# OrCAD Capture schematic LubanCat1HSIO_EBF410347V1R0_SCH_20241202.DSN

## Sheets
1 04 邮票孔连接器: size A4; title: 野火鲁班猫1HS.邮票孔核心板; rev: V1.0; note: 邮票孔连接器; note: https://yehuosm.tmall.com
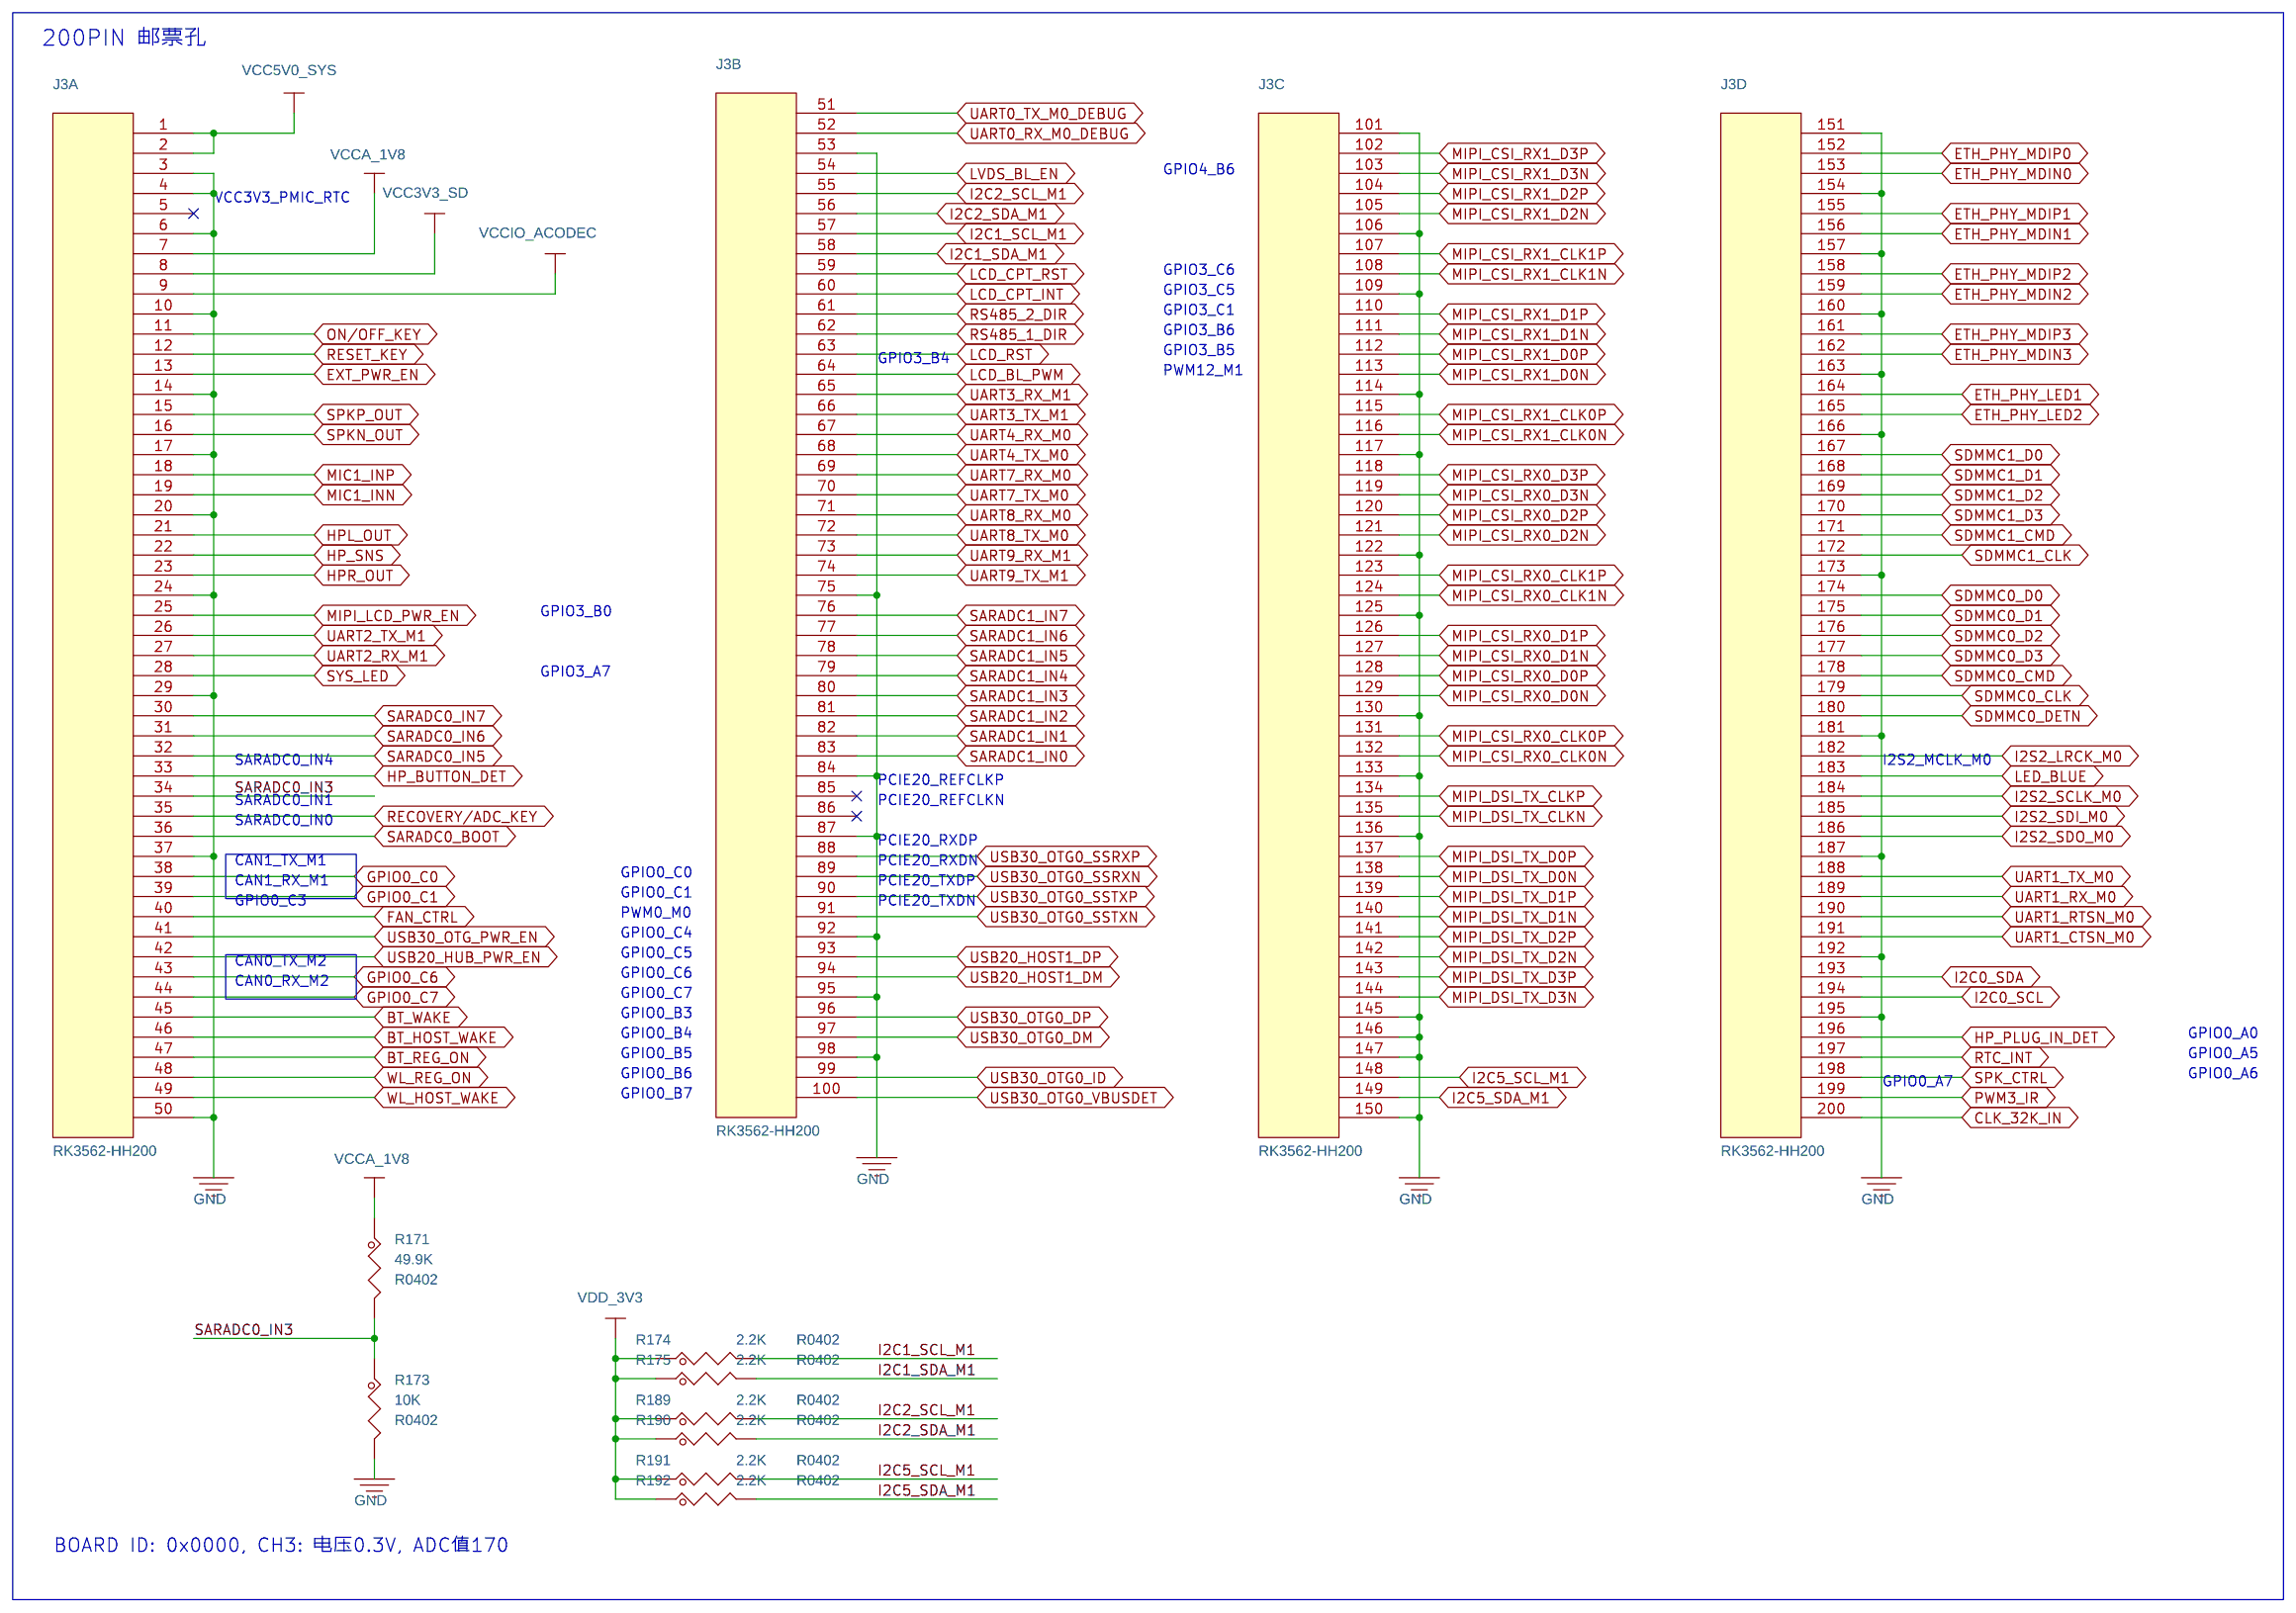
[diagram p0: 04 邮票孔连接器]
2 12 UART/RS232/RS485: size A4; title: 野火鲁班猫1HS.邮票孔底板; note: UART/RS232/RS485
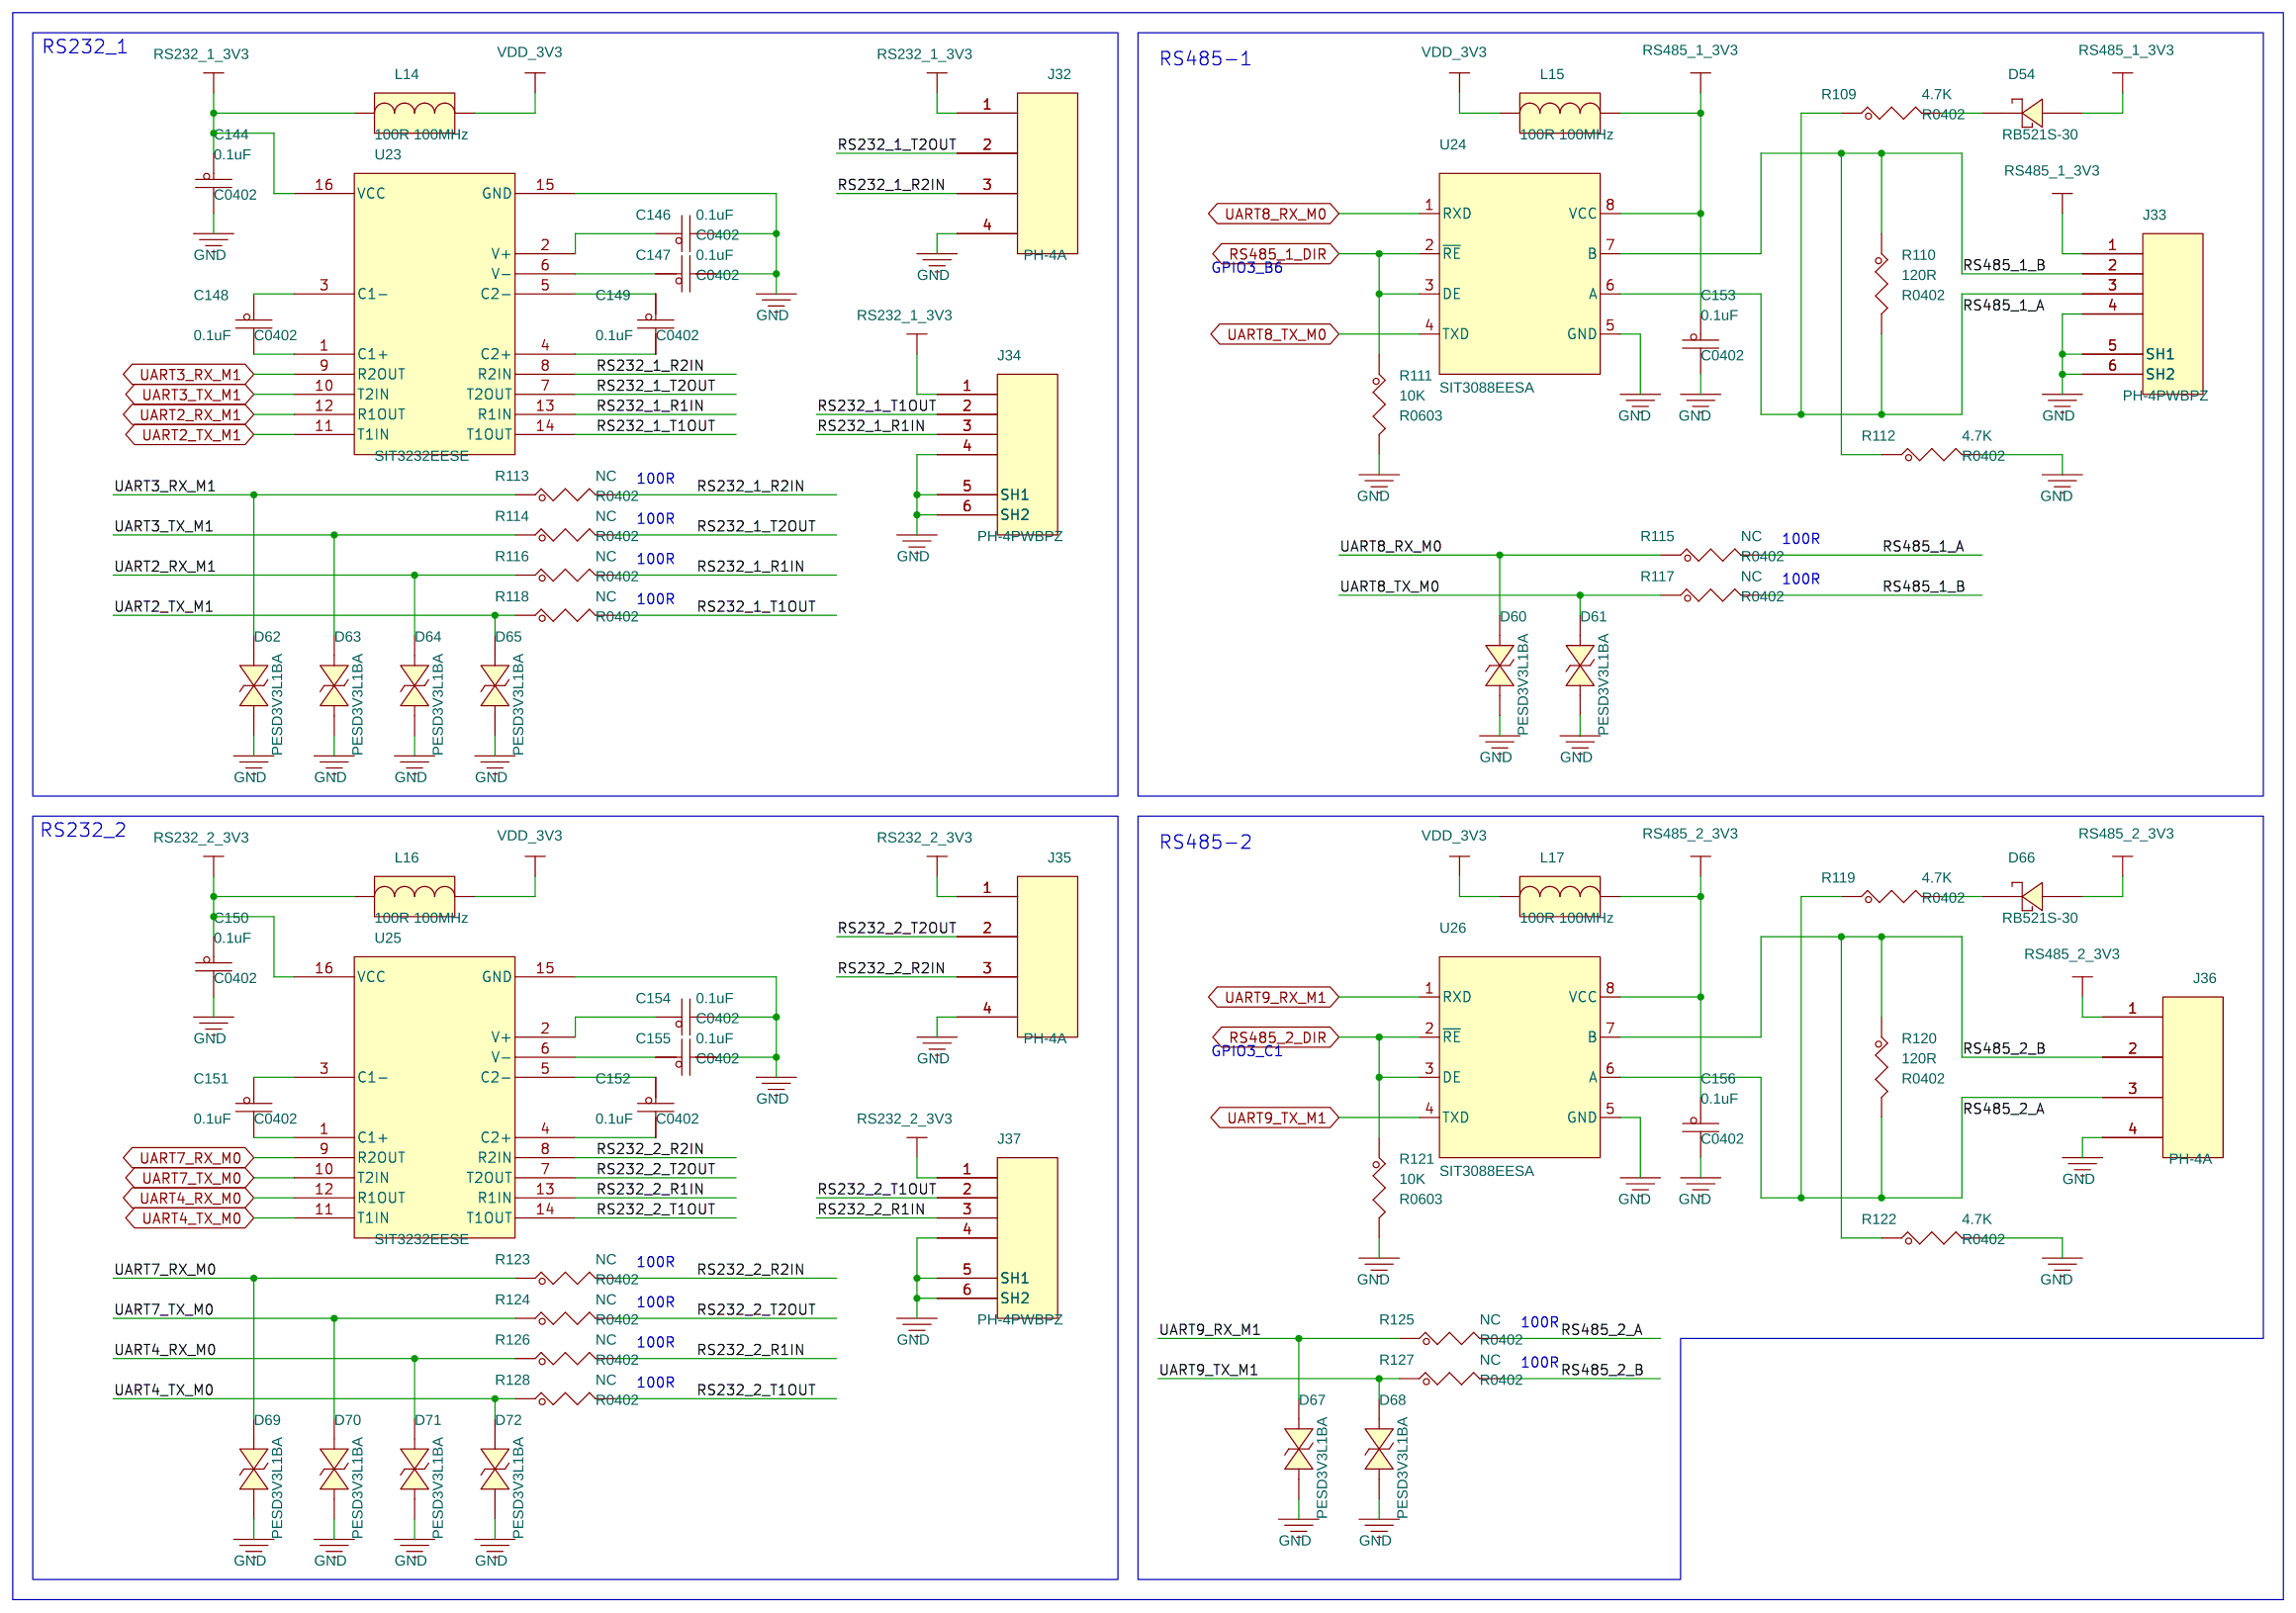
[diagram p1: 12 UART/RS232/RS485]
3 07 USB3.0 OTG/USB2.0 HUB/DEBUG: size A3; title: 野火鲁班猫1HS.邮票孔底板; note: USB3.0 OTG/USB2.0 HUB/DEBUG
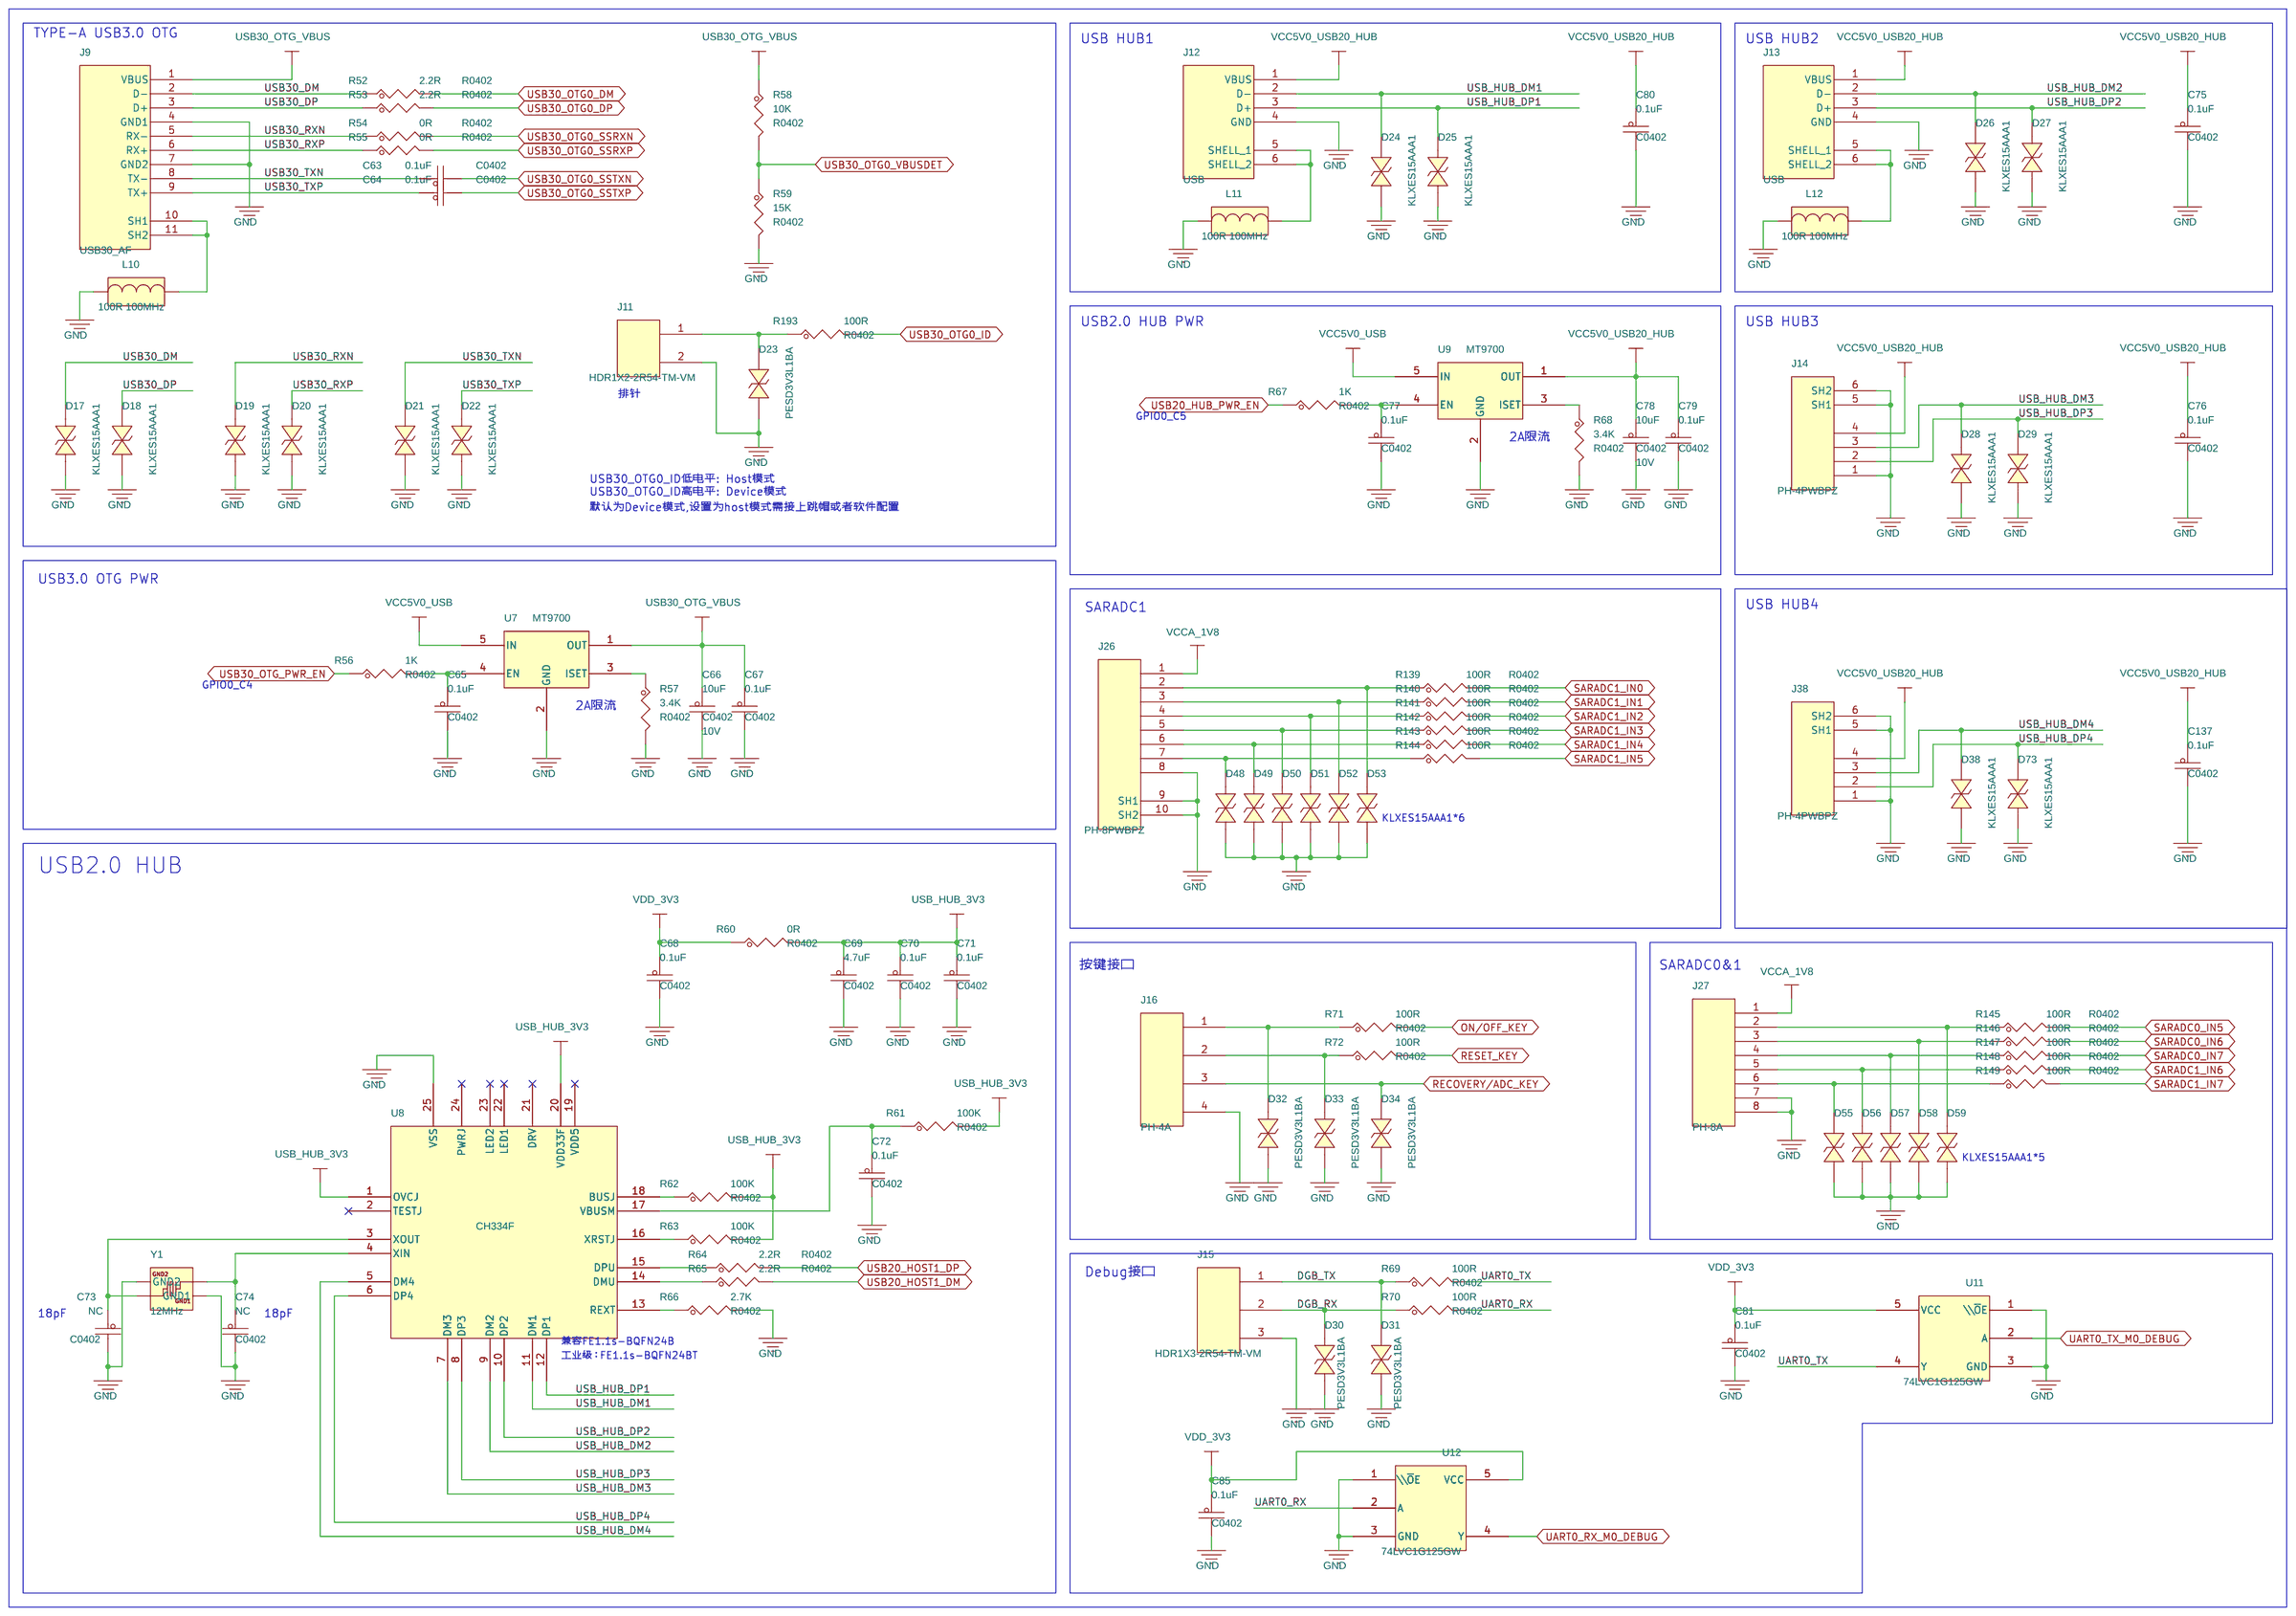
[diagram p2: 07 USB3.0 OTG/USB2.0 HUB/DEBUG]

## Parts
sheet 04 邮票孔连接器
J3  RK3562-HH200  [HH200-0R90-48R1X48R1-B]  (sections A,B,C,D)
R171  49.9K  [R0402]
R173  10K  [R0402]
R174  2.2K  [R0402]
R175  2.2K  [R0402]
R189  2.2K  [R0402]
R190  2.2K  [R0402]
R191  2.2K  [R0402]
R192  2.2K  [R0402]
sheet 07 USB3.0 OTG/USB2.0 HUB/DEBUG
C63  0.1uF  [C0402]
C64  0.1uF  [C0402]
C65  0.1uF  [C0402]
C66  10uF  [C0402]
C67  0.1uF  [C0402]
C68  0.1uF  [C0402]
C69  4.7uF  [C0402]
C70  0.1uF  [C0402]
C71  0.1uF  [C0402]
C72  0.1uF  [C0402]
C73  NC  [C0402]
C74  NC  [C0402]
C75  0.1uF  [C0402]
C76  0.1uF  [C0402]
C77  0.1uF  [C0402]
C78  10uF  [C0402]
C79  0.1uF  [C0402]
C80  0.1uF  [C0402]
C81  0.1uF  [C0402]
C85  0.1uF  [C0402]
C137  0.1uF  [C0402]
D17  KLXES15AAA1  [ES0402]
D18  KLXES15AAA1  [ES0402]
D19  KLXES15AAA1  [ES0402]
D20  KLXES15AAA1  [ES0402]
D21  KLXES15AAA1  [ES0402]
D22  KLXES15AAA1  [ES0402]
D23  PESD3V3L1BA  [sod323_t]
D24  KLXES15AAA1  [ES0402]
D25  KLXES15AAA1  [ES0402]
D26  KLXES15AAA1  [ES0402]
D27  KLXES15AAA1  [ES0402]
D28  KLXES15AAA1  [ES0402]
D29  KLXES15AAA1  [ES0402]
D30  PESD3V3L1BA  [sod323_t]
D31  PESD3V3L1BA  [sod323_t]
D32  PESD3V3L1BA  [sod323_t]
D33  PESD3V3L1BA  [sod323_t]
D34  PESD3V3L1BA  [sod323_t]
D38  KLXES15AAA1  [ES0402]
D48  KLXES15AAA1  [ES0402]
D49  KLXES15AAA1  [ES0402]
D50  KLXES15AAA1  [ES0402]
D51  KLXES15AAA1  [ES0402]
D52  KLXES15AAA1  [ES0402]
D53  KLXES15AAA1  [ES0402]
D55  KLXES15AAA1  [ES0402]
D56  KLXES15AAA1  [ES0402]
D57  KLXES15AAA1  [ES0402]
D58  KLXES15AAA1  [ES0402]
D59  KLXES15AAA1  [ES0402]
D73  KLXES15AAA1  [ES0402]
J9  USB30_AF  [USB9-A-16R5X14R45-TM]
J11  HDR1X2-2R54-TM-VM  [HDR1X2-2R54-TM-VM]
J12  USB  [USB-A-SM]
J13  USB  [USB-A-SM]
J14  PH-4PWBPZ  [ph2r0-a-1x4]
J15  HDR1X3-2R54-TM-VM  [HDR1X3-2R54-TM-VM]
J16  PH-4A  [PH-1X4-2P0]
J26  PH-8PWBPZ  [PH2R0-A-1X8]
J27  PH-8A  [ph-1x8-2p0]
J38  PH-4PWBPZ  [ph2r0-a-1x4]
L10  100R 100MHz  [L0603]
L11  100R 100MHz  [L0603]
L12  100R 100MHz  [L0603]
R52  2.2R  [R0402]
R53  2.2R  [R0402]
R54  0R  [R0402]
R55  0R  [R0402]
R56  1K  [R0402]
R57  3.4K  [R0402]
R58  10K  [R0402]
R59  15K  [R0402]
R60  0R  [R0402]
R61  100K  [R0402]
R62  100K  [R0402]
R63  100K  [R0402]
R64  2.2R  [R0402]
R65  2.2R  [R0402]
R66  2.7K  [R0402]
R67  1K  [R0402]
R68  3.4K  [R0402]
R69  100R  [R0402]
R70  100R  [R0402]
R71  100R  [R0402]
R72  100R  [R0402]
R139  100R  [R0402]
R140  100R  [R0402]
R141  100R  [R0402]
R142  100R  [R0402]
R143  100R  [R0402]
R144  100R  [R0402]
R145  100R  [R0402]
R146  100R  [R0402]
R147  100R  [R0402]
R148  100R  [R0402]
R149  100R  [R0402]
R193  100R  [R0402]
U7  MT9700  [SOT23-5]
U8  CH334F  [QFN24]
U9  MT9700  [SOT23-5]
U11  74LVC1G125GW  [SOT-353]
U12  74LVC1G125GW  [SOT-353]
Y1  12MHz  [3225]
sheet 12 UART/RS232/RS485
C144  0.1uF  [C0402]
C146  0.1uF  [C0402]
C147  0.1uF  [C0402]
C148  0.1uF  [C0402]
C149  0.1uF  [C0402]
C150  0.1uF  [C0402]
C151  0.1uF  [C0402]
C152  0.1uF  [C0402]
C153  0.1uF  [C0402]
C154  0.1uF  [C0402]
C155  0.1uF  [C0402]
C156  0.1uF  [C0402]
D54  RB521S-30  [SOD523]
D60  PESD3V3L1BA  [sod323_t]
D61  PESD3V3L1BA  [sod323_t]
D62  PESD3V3L1BA  [sod323_t]
D63  PESD3V3L1BA  [sod323_t]
D64  PESD3V3L1BA  [sod323_t]
D65  PESD3V3L1BA  [sod323_t]
D66  RB521S-30  [SOD523]
D67  PESD3V3L1BA  [sod323_t]
D68  PESD3V3L1BA  [sod323_t]
D69  PESD3V3L1BA  [sod323_t]
D70  PESD3V3L1BA  [sod323_t]
D71  PESD3V3L1BA  [sod323_t]
D72  PESD3V3L1BA  [sod323_t]
J32  PH-4A  [PH-1X4-2P0]
J33  PH-4PWBPZ  [ph2r0-a-1x4]
J34  PH-4PWBPZ  [ph2r0-a-1x4]
J35  PH-4A  [PH-1X4-2P0]
J36  PH-4A  [PH-1X4-2P0]
J37  PH-4PWBPZ  [ph2r0-a-1x4]
L14  100R 100MHz  [L0603]
L15  100R 100MHz  [L0603]
L16  100R 100MHz  [L0603]
L17  100R 100MHz  [L0603]
R109  4.7K  [R0402]
R110  120R  [R0402]
R111  10K  [R0603]
R112  4.7K  [R0402]
R113  NC  [R0402]
R114  NC  [R0402]
R115  NC  [R0402]
R116  NC  [R0402]
R117  NC  [R0402]
R118  NC  [R0402]
R119  4.7K  [R0402]
R120  120R  [R0402]
R121  10K  [R0603]
R122  4.7K  [R0402]
R123  NC  [R0402]
R124  NC  [R0402]
R125  NC  [R0402]
R126  NC  [R0402]
R127  NC  [R0402]
R128  NC  [R0402]
U23  SIT3232EESE  [SOIC16]
U24  SIT3088EESA  [SOP8]
U25  SIT3232EESE  [SOIC16]
U26  SIT3088EESA  [SOP8]

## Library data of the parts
J3 = RK3562-HH200: 备注: 鲁班猫1HS; 规格: RK3562邮票孔核心板 引脚数量200P 引脚间距0.9mm 尺寸48.1x48.1mm; 类别: 邮票孔核心板; 品牌: 野火; 生命周期: 量产; 条码: EBFCIS240902134638
R171 = RES: 规格: 贴片电阻49.9K 1% 1/16W 0402; 规格编号: RMC040249.9K1%N; 规格书: 幸亚电阻.pdf; 价格: 0.015936; 类别: 贴片电阻0402; 品牌: 幸亚; 生命周期: 量产; 条码: EBF29070257
R58 R173 = RES: 规格: 贴片电阻10K 1% 1/16W 0402; 规格编号: 0402WGF1002TCE; 规格书: 厚声-无铅厚膜电阻.pdf; 价格: 0.002773; 类别: 贴片电阻0402; 品牌: 厚声; 生命周期: 量产; 条码: EBF29070046
R174 R175 R189-R192 = RES: 规格: 贴片电阻2.2K 1% 1/16W 0402; 规格编号: RI0402L2201FT; 规格书: 合科泰-RI系列电阻.pdf; 类别: 贴片电阻0402; 品牌: 合科泰; 生命周期: 量产; 条码: EBF29070051
C63-C65 C67 C68 C70-C72 C75-C77 C79-C81 C85 C137 C144 C146-C156 = CAP_NP: voltage: 10V; 备注: H743挑战者; 规格: 贴片电容0.1uF 10% 10V X7R 0402; 规格编号: 0402B104K100NT; 规格书: 风华电容.pdf; 价格: 0.003175; 类别: 贴片电容0402; 品牌: 风华; 生命周期: 量产; 条码: EBFCIS230603155031
C66 C78 = CAP_NP: Voltage: 10V; 规格: 贴片电容10uF 20% 10V X5R 0402; 规格编号: CL05A106MP8NUB8; 规格书: 三星电容.pdf; 价格: 0.518415; 类别: 贴片电容0402; 品牌: 三星; 生命周期: 量产; 条码: EBF29060247
C69 = CAP_NP: voltage: 10V; 规格: 贴片电容4.7uF 10% 10V X5R 0402; 规格编号: CC0402KRX5R6BB475; 规格书: 国巨-贴片电容.pdf; 价格: 0.059058; 类别: 贴片电容0402; 品牌: 国巨; 生命周期: 量产; 条码: EBF29060248
C73 C74 = CAP_NP: 规格: 贴片电容NC 预留; 类别: 贴片电容0402; 条码: EBF29060149
D17-D22 D24-D29 D38 D48-D53 D55-D59 D73 = DIODE_BI-DIR_TRIG: 规格: 用于 USB3.0、HDMI 0.5pF、5V、±15kV ESD 保护二极管; 规格书: KLXES15AAA1.pdf; 价格: 0.09719; 类别: 贴片ESD; 品牌: 永裕泰; 生命周期: 量产; 条码: EBF29140063
D23 D30-D34 D60-D65 D67-D72 = DIODE_BI-DIR_TRIG: 规格: 防静电保护ESD二极管 箝位电压26V 击穿电压5.8V 反向关断电压3.3V; 规格编号: PESD3V3L1BA 115; 规格书: 安世-PESD3V3L1BA-115.pdf; 价格: 0.31497; 类别: 贴片ESD; 品牌: 安世; 生命周期: 量产; 丝印: AB; 条码: EBF29140003
J9 = USB30_AF: 备注: RK3566广告机; 规格: USB3.0 Type-A 母座 AF 90°弯插 蓝胶 触点数量9; 规格编号: USB-301WD-ARY; 规格书: 讯普_USB3.0-TYPE-A母座弯插.pdf; 类别: USB接口; 品牌: 讯普; 生命周期: 量产; 条码: EBFCIS230517183858
J11 = 1X2PIN: 规格: 蓝色直插单排排针 总PIN数2 间距2.54mm; 规格编号: HDR1X2-2R54-TM-VM-BLUE; 规格书: 州日_单排针_直插_2P54.pdf; 价格: 0.02; 类别: 2.54mm直插单排排针; 品牌: 州日; 生命周期: 量产; 条码: EBF29020019
J12 J13 = USB_Conn.-Fem-TypeA-TH-RA: 规格: Type-A 母座 AF90°弯插 白胶 卷边有后盖 铁壳 触点数量4 额定电流1.5A; 规格编号: USB-U212-BJS; 规格书: TYPE-A母座AF90°弯插白胶卷边有后盖铁壳.pdf; 类别: USB接口; 品牌: 汉博; 生命周期: 量产; 条码: EBF29040127
J14 J33 J34 J37 J38 = 1X4PIN_SH: 规格: 间距：2mm 插针结构：1x4P 排数：1 每排PIN数：4 公母：公型插针 安装方式：卧贴 额定电流：2A 工作温度范围：-25℃~+85℃; 规格书: 博穆精密_PH2.0-A.pdf; 价格: 0.23158; 类别: PH连接器; 品牌: 博穆精密; 生命周期: 量产; 条码: EBF29040117
J15 = 1X3PIN: 规格: 蓝色直插单排排针 总PIN数3 间距2.54mm; 规格编号: HDR1X3-2R54-TM-VM-BLUE; 规格书: 州日_单排针_直插_2P54.pdf; 价格: 0.06; 类别: 2.54mm直插单排排针; 品牌: 州日; 生命周期: 量产; 条码: EBF29020046
J16 J32 J35 J36 = 1X4PIN: 规格: 直针PH2.0-4P 间距2.0MM 拔插式 接插件; 规格书: 博穆精密-PH2.0.pdf; 价格: 0.017; 可替代料: EBF29020025; 类别: PH连接器; 品牌: 博穆精密; 生命周期: 量产; 条码: EBF29020025
J26 = 1X8PIN_SH: 备注: RK3562邮票孔底板; 规格: 间距：2mm 插针结构：1x8P 排数：1 每排PIN数：8 公母：公型插针 安装方式：卧贴 额定电流：2A 工作温度范围：-25℃~+85℃; 规格书: 博穆精密_PH2.0-A.pdf; 价格: 0.648177; 类别: PH连接器; 品牌: 博穆精密; 生命周期: 量产; 条码: EBFCIS230829011841
J27 = 1X8PIN: 备注: RK3562邮票孔底板; 规格: 直针PH2.0-8P 间距2.0MM 拔插式 接插件; 规格书: 博穆精密-PH2.0.pdf; 价格: 0.206072; 类别: PH连接器; 品牌: 博穆精密; 生命周期: 量产; 条码: EBFCIS230829011232
L10-L12 L14-L17 = BEAD: 规格: 磁珠100Ω @100MHz 额定电流3A 直流电阻30mΩ; 规格编号: UPZ1608E101-3R0TF; 规格书: 顺络-磁珠.pdf; 价格: 0.021567; 类别: 贴片磁珠0603; 品牌: 顺络; 生命周期: 量产; 条码: EBF29050038
R52 R53 R64 R65 = RES: 规格: 贴片电阻2.2R 1% 1/16W 0402; 规格编号: 0402WGF220KTCE; 规格书: 厚声-无铅厚膜电阻.pdf; 价格: 0.003072; 类别: 贴片电阻0402; 品牌: 厚声; 生命周期: 量产; 条码: EBF29070280
R54 R55 R60 = RES: 规格: 贴片电阻0R 1% 1/16W 0402; 规格编号: RI0402L000FT; 规格书: 合科泰-RI系列电阻.pdf; 类别: 贴片电阻0402; 品牌: 合科泰; 生命周期: 量产; 条码: EBF29070049
R56 R67 = RES: 规格: 贴片电阻1K 1% 1/16W 0402; 规格编号: RI0402L1001FT; 规格书: 合科泰-RI系列电阻.pdf; 类别: 贴片电阻0402; 品牌: 合科泰; 生命周期: 量产; 条码: EBF29070050
R57 R68 = RES: 规格: 贴片电阻3.4K 1% 1/16W 0402; 规格编号: RI0402L3401FT; 规格书: 合科泰-RI系列电阻.pdf; 类别: 贴片电阻0402; 品牌: 合科泰; 生命周期: 量产; 条码: EBF29070186
R59 = RES: 规格: 贴片电阻15K 1% 1/16W 0402; 规格编号: RI0402L1502FT; 规格书: 合科泰-RI系列电阻.pdf; 类别: 贴片电阻0402; 品牌: 合科泰; 生命周期: 量产; 条码: EBF29070222
R61-R63 = RES: 规格: 贴片电阻100K 1% 1/16W 0402; 规格编号: RI0402L1003FT; 规格书: 合科泰-RI系列电阻.pdf; 类别: 贴片电阻0402; 品牌: 合科泰; 生命周期: 量产; 条码: EBF29070054
R66 = RES: 规格: 贴片电阻2.7K 1% 1/16W 0402; 规格编号: RMC04022.7K1%N; 规格书: 幸亚电阻.pdf; 价格: 0.016497; 类别: 贴片电阻0402; 品牌: 幸亚; 生命周期: 量产; 条码: EBF29070202
R69-R72 R139-R149 R193 = RES: 规格: 贴片电阻100R 1% 1/16W 0402; 规格编号: RI0402L1000FT; 规格书: 合科泰-RI系列电阻.pdf; 类别: 贴片电阻0402; 品牌: 合科泰; 生命周期: 量产; 条码: EBF29070053
U7 U9 = MT9700: 规格: 负载开关 工作电压2.4V-5.5V 最大电流2A 过流保护; 规格书: MT9700.pdf; 价格: 0.483492; 类别: 功率开关; 品牌: 西安航天民芯; 生命周期: 量产; 丝印: D00HA-X; 条码: EBF29280004
U8 = FE1.1s-BQFN24B: 规格: USB HUB芯片 工作电压3.3V 5V 协议类别USB2.0 支持高速(480Mbps) 全速(12Mbps)和低速(1.5Mbps)模式; 规格书: 南京沁恒_CH334F.pdf; 类别: USB芯片; 品牌: 南京沁恒; 生命周期: 量产; 条码: EBFCIS221222095807
U11 U12 = 74LVC1G125: 规格: 时钟缓冲器 驱动器 具有三态输出 允许工作电压为3.3V 5.5V 典型工作电流100mA; 规格书: 74LVC1G125GW.pdf; 价格: 0.182409; 类别: 隔离器件; 品牌: 安世; 生命周期: 量产; 丝印: VM; 条码: EBF29170001
Y1 = CRYSTAL_4P: 规格: 无源晶振12MHZ ±10ppm 80Ω 20pF -20℃~+70℃ 3225; 规格编号: RL3225-12M; 规格书: 创捷_3225贴片晶振.pdf; 可替代料: EBF29100013; 类别: 贴片晶振 3225; 品牌: 创捷; 生命周期: 量产; 条码: EBFCIS241228135855
D54 D66 = DIODE_SCHTKY: 规格: 直流反向耐压(Vr)：30V 平均整流电流(Io)：200mA 正向压降(Vf)：500mV@200mA 30V@100mA,VF=350mV@10mA; 规格书: 江苏长电_RB521S-30.pdf; 价格: 0.06781; 类别: 贴片肖特基二极管; 品牌: 江苏长电; 生命周期: 量产; 条码: EBFCIS221114153437
R109 R112 R119 R122 = RES: 规格: 贴片电阻4.7K 1% 1/16W 0402; 规格编号: RI0402L4701FT; 规格书: 合科泰-RI系列电阻.pdf; 类别: 贴片电阻0402; 品牌: 合科泰; 生命周期: 量产; 条码: EBF29070047
R110 R120 = RES: 规格: 贴片电阻120R 1% 1/16W 0402; 规格编号: 0402WGF1200TCE; 规格书: 厚声-无铅厚膜电阻.pdf; 价格: 0.002198; 类别: 贴片电阻0402; 品牌: 厚声; 生命周期: 量产; 条码: EBF29070275
R111 R121 = RES: 规格: 贴片电阻10K 1% 1/10W 0603; 规格编号: RI0603L1002FT; 规格书: 合科泰-RI系列电阻.pdf; 类别: 贴片电阻0603; 品牌: 合科泰; 生命周期: 量产; 条码: EBF29070074
R113-R118 R123-R128 = RES: 规格: 贴片电阻NC 预留; 类别: 贴片电阻0402; 条码: EBF29070087
U23 U25 = MAX3232CSE: 备注: 鲁班猫; 规格: RS232芯片 收发器 驱动器/接收器数：2/2 协议类别RS232 电源电压3.0V~5.5V 数据速率96kbps; 规格书: 芯力特_SIT3232E-V1.17-cn.pdf; 类别: RS232芯片; 品牌: 芯力特; 生命周期: 量产; 条码: EBFCIS231207155139
U24 U26 = SIT3088E-8P: 备注: 鲁班猫; 规格: RS-485/RS-422芯片 收发器 允许256个器件连接总线 协议类别RS-485 电源电压3.0V~5.5V 数据速率14Mbps; 规格书: 芯力特_SIT3088E-V1.8_cn.pdf; 类别: RS485/RS422芯片; 品牌: 芯力特; 生命周期: 量产; 条码: EBFCIS231207153322

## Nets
GND: C65.2 C66.2 C67.2 C68.2 C69.2 C70.2 C71.2 C72.2 C73.2 C74.2 C75.2 C76.2 C77.2 C78.2 C79.2 C80.2 C81.2 C85.2 C137.2 C144.2 C146.2 C147.2 C150.2 C153.2 C154.2 C155.2 C156.2 D17.2 D18.2 D19.2 D20.2 D21.2 D22.2 D23.2 D24.2 D25.2 D26.2 D27.2 D28.2 D29.2 D30.2 D31.2 D32.2 D33.2 D34.2 D38.2 D48.2 D49.2 D50.2 D51.2 D52.2 D53.2 D55.2 D56.2 D57.2 D58.2 D59.2 D60.2 D61.2 D62.2 D63.2 D64.2 D65.2 D67.2 D68.2 D69.2 D70.2 D71.2 D72.2 D73.2 J3.3 J3.4 J3.6 J3.10 J3.14 J3.17 J3.20 J3.24 J3.29 J3.37 J3.50 J3.53 J3.75 J3.84 J3.87 J3.92 J3.95 J3.98 J3.101 J3.106 J3.109 J3.114 J3.117 J3.122 J3.125 J3.130 J3.133 J3.136 J3.145 J3.146 J3.147 J3.150 J3.151 J3.154 J3.157 J3.160 J3.163 J3.166 J3.173 J3.181 J3.187 J3.192 J3.195 J9.4(GND1) J9.7(GND2) J11.2 J12.4(GND) J13.4(GND) J14.1 J14.5(SH1) J14.6(SH2) J15.3 J16.4 J26.8 J26.9(SH1) J26.10(SH2) J27.7 J27.8 J32.4 J33.4 J33.5(SH1) J33.6(SH2) J34.4 J34.5(SH1) J34.6(SH2) J35.4 J36.4 J37.4 J37.5(SH1) J37.6(SH2) J38.1 J38.5(SH1) J38.6(SH2) L10.1 L11.1 L12.1 R57.2 R59.2 R66.2 R68.2 R111.2 R112.2 R121.2 R122.2 R173.2 U7.2(GND) U8.25(VSS) U9.2(GND) U11.1(\\~{O}E) U11.3(GND) U12.1(\\~{O}E) U12.3(GND) U23.15(GND) U24.5(GND) U25.15(GND) U26.5(GND) Y1.2(GND1) Y1.4(GND2)
VCC3V3_SD: J3.8
VCC5V0_SYS: J3.1 J3.2
VCC5V0_USB: U7.5(IN) U9.5(IN)
VCC5V0_USB20_HUB: C75.1 C76.1 C78.1 C79.1 C80.1 C137.1 J12.1(VBUS) J13.1(VBUS) J14.4 J38.4 U9.1(OUT)
VCCA_1V8: J3.7 J26.1 J27.1 R171.1
VCCIO_ACODEC: J3.9
VDD_3V3: C68.1 C81.1 C85.1 L14.2 L15.1 L16.2 L17.1 R60.1 R174.1 R175.1 R189.1 R190.1 R191.1 R192.1 U11.5(VCC) U12.5(VCC)
BT_HOST_WAKE: J3.46
BT_REG_ON: J3.47
BT_WAKE: J3.45
CLK_32K_IN: J3.200
DGB_RX: D30.1 J15.2 R70.1
DGB_TX: D31.1 J15.1 R69.1
ETH_PHY_LED1: J3.164
ETH_PHY_LED2: J3.165
ETH_PHY_MDIN0: J3.153
ETH_PHY_MDIN1: J3.156
ETH_PHY_MDIN2: J3.159
ETH_PHY_MDIN3: J3.162
ETH_PHY_MDIP0: J3.152
ETH_PHY_MDIP1: J3.155
ETH_PHY_MDIP2: J3.158
ETH_PHY_MDIP3: J3.161
EXT_PWR_EN: J3.13
FAN_CTRL: J3.40
GPIO0_C0: J3.38
GPIO0_C1: J3.39
GPIO0_C6: J3.43
GPIO0_C7: J3.44
HP_BUTTON_DET: J3.33
HP_PLUG_IN_DET: J3.196
HP_SNS: J3.22
HPL_OUT: J3.21
HPR_OUT: J3.23
I2C0_SCL: J3.194
I2C0_SDA: J3.193
I2C1_SCL_M1: J3.57 R174.2
I2C1_SDA_M1: J3.58 R175.2
I2C2_SCL_M1: J3.55 R189.2
I2C2_SDA_M1: J3.56 R190.2
I2C5_SCL_M1: J3.148 R191.2
I2C5_SDA_M1: J3.149 R192.2
I2S2_LRCK_M0: J3.182
I2S2_SCLK_M0: J3.184
I2S2_SDI_M0: J3.185
I2S2_SDO_M0: J3.186
LCD_BL_PWM: J3.64
LCD_CPT_INT: J3.60
LCD_CPT_RST: J3.59
LCD_RST: J3.63
LED_BLUE: J3.183
LVDS_BL_EN: J3.54
MIC1_INN: J3.19
MIC1_INP: J3.18
MIPI_CSI_RX0_CLK0N: J3.132
MIPI_CSI_RX0_CLK0P: J3.131
MIPI_CSI_RX0_CLK1N: J3.124
MIPI_CSI_RX0_CLK1P: J3.123
MIPI_CSI_RX0_D0N: J3.129
MIPI_CSI_RX0_D0P: J3.128
MIPI_CSI_RX0_D1N: J3.127
MIPI_CSI_RX0_D1P: J3.126
MIPI_CSI_RX0_D2N: J3.121
MIPI_CSI_RX0_D2P: J3.120
MIPI_CSI_RX0_D3N: J3.119
MIPI_CSI_RX0_D3P: J3.118
MIPI_CSI_RX1_CLK0N: J3.116
MIPI_CSI_RX1_CLK0P: J3.115
MIPI_CSI_RX1_CLK1N: J3.108
MIPI_CSI_RX1_CLK1P: J3.107
MIPI_CSI_RX1_D0N: J3.113
MIPI_CSI_RX1_D0P: J3.112
MIPI_CSI_RX1_D1N: J3.111
MIPI_CSI_RX1_D1P: J3.110
MIPI_CSI_RX1_D2N: J3.105
MIPI_CSI_RX1_D2P: J3.104
MIPI_CSI_RX1_D3N: J3.103
MIPI_CSI_RX1_D3P: J3.102
MIPI_DSI_TX_CLKN: J3.135
MIPI_DSI_TX_CLKP: J3.134
MIPI_DSI_TX_D0N: J3.138
MIPI_DSI_TX_D0P: J3.137
MIPI_DSI_TX_D1N: J3.140
MIPI_DSI_TX_D1P: J3.139
MIPI_DSI_TX_D2N: J3.142
MIPI_DSI_TX_D2P: J3.141
MIPI_DSI_TX_D3N: J3.144
MIPI_DSI_TX_D3P: J3.143
MIPI_LCD_PWR_EN: J3.25
ON/OFF_KEY: J3.11 R71.2
PWM3_IR: J3.199
RECOVERY/ADC_KEY: D34.1 J3.35 J16.3
RESET_KEY: J3.12 R72.2
RS232_1_3V3: C144.1 J32.1 J34.1 L14.1 U23.16(VCC)
RS232_1_R1IN: J34.3 R116.2 U23.13(R1IN)
RS232_1_R2IN: J32.3 R113.2 U23.8(R2IN)
RS232_1_T1OUT: J34.2 R118.2 U23.14(T1OUT)
RS232_1_T2OUT: J32.2 R114.2 U23.7(T2OUT)
RS232_2_3V3: C150.1 J35.1 J37.1 L16.1 U25.16(VCC)
RS232_2_R1IN: J37.3 R126.2 U25.13(R1IN)
RS232_2_R2IN: J35.3 R123.2 U25.8(R2IN)
RS232_2_T1OUT: J37.2 R128.2 U25.14(T1OUT)
RS232_2_T2OUT: J35.2 R124.2 U25.7(T2OUT)
RS485_1_3V3: C153.1 D54.2 J33.1 L15.2 U24.8(VCC)
RS485_1_A: J33.3 R109.1 R110.2 R115.2 U24.6(A)
RS485_1_B: J33.2 R110.1 R112.1 R117.2 U24.7(B)
RS485_1_DIR: J3.62 R111.1 U24.2(~{RE}) U24.3(DE)
RS485_2_3V3: C156.1 D66.2 J36.1 L17.2 U26.8(VCC)
RS485_2_A: J36.3 R119.1 R120.2 R125.2 U26.6(A)
RS485_2_B: J36.2 R120.1 R122.1 R127.2 U26.7(B)
RS485_2_DIR: J3.61 R121.1 U26.2(~{RE}) U26.3(DE)
RTC_INT: J3.197
SARADC0_BOOT: J3.36
SARADC0_IN3: J3.34 R171.2 R173.1
SARADC0_IN5: J3.32 R145.2
SARADC0_IN6: J3.31 R146.2
SARADC0_IN7: J3.30 R147.2
SARADC1_IN0: J3.83 R139.2
SARADC1_IN1: J3.82 R140.2
SARADC1_IN2: J3.81 R141.2
SARADC1_IN3: J3.80 R142.2
SARADC1_IN4: J3.79 R143.2
SARADC1_IN5: J3.78 R144.2
SARADC1_IN6: J3.77 R148.2
SARADC1_IN7: J3.76 R149.2
SDMMC0_CLK: J3.179
SDMMC0_CMD: J3.178
SDMMC0_D0: J3.174
SDMMC0_D1: J3.175
SDMMC0_D2: J3.176
SDMMC0_D3: J3.177
SDMMC0_DETN: J3.180
SDMMC1_CLK: J3.172
SDMMC1_CMD: J3.171
SDMMC1_D0: J3.167
SDMMC1_D1: J3.168
SDMMC1_D2: J3.169
SDMMC1_D3: J3.170
SPK_CTRL: J3.198
SPKN_OUT: J3.16
SPKP_OUT: J3.15
SYS_LED: J3.28
UART0_RX: R70.2 U12.2(A)
UART0_RX_M0_DEBUG: J3.52 U12.4(Y)
UART0_TX: R69.2 U11.4(Y)
UART0_TX_M0_DEBUG: J3.51 U11.2(A)
UART1_CTSN_M0: J3.191
UART1_RTSN_M0: J3.190
UART1_RX_M0: J3.189
UART1_TX_M0: J3.188
UART2_RX_M1: D64.1 J3.27 R116.1 U23.12(R1OUT)
UART2_TX_M1: D65.1 J3.26 R118.1 U23.11(T1IN)
UART3_RX_M1: D62.1 J3.65 R113.1 U23.9(R2OUT)
UART3_TX_M1: D63.1 J3.66 R114.1 U23.10(T2IN)
UART4_RX_M0: D71.1 J3.67 R126.1 U25.12(R1OUT)
UART4_TX_M0: D72.1 J3.68 R128.1 U25.11(T1IN)
UART7_RX_M0: D69.1 J3.69 R123.1 U25.9(R2OUT)
UART7_TX_M0: D70.1 J3.70 R124.1 U25.10(T2IN)
UART8_RX_M0: D60.1 J3.71 R115.1 U24.1(RXD)
UART8_TX_M0: D61.1 J3.72 R117.1 U24.4(TXD)
UART9_RX_M1: D67.1 J3.73 R125.1 U26.1(RXD)
UART9_TX_M1: D68.1 J3.74 R127.1 U26.4(TXD)
USB20_HOST1_DM: J3.94 R65.2
USB20_HOST1_DP: J3.93 R64.2
USB20_HUB_PWR_EN: J3.42 R67.1
USB30_DM: D17.1 J9.2(D-) R52.1
USB30_DP: D18.1 J9.3(D+) R53.1
USB30_OTG0_DM: J3.97 R52.2
USB30_OTG0_DP: J3.96 R53.2
USB30_OTG0_ID: J3.99 R193.2
USB30_OTG0_SSRXN: J3.89 R54.2
USB30_OTG0_SSRXP: J3.88 R55.2
USB30_OTG0_SSTXN: C63.2 J3.91
USB30_OTG0_SSTXP: C64.2 J3.90
USB30_OTG0_VBUSDET: J3.100 R58.2 R59.1
USB30_OTG_PWR_EN: J3.41 R56.1
USB30_OTG_VBUS: C66.1 C67.1 J9.1(VBUS) R58.1 U7.1(OUT)
USB30_RXN: D19.1 J9.5(RX-) R54.1
USB30_RXP: D20.1 J9.6(RX+) R55.1
USB30_TXN: C63.1 D21.1 J9.8(TX-)
USB30_TXP: C64.1 D22.1 J9.9(TX+)
USB_HUB_3V3: C69.1 C70.1 C71.1 R60.2 R61.2 R62.2 R63.2 U8.1(OVCJ) U8.20(VDD33F)
USB_HUB_DM1: D24.1 J12.2(D-) U8.11(DM1)
USB_HUB_DM2: D26.1 J13.2(D-) U8.9(DM2)
USB_HUB_DM3: D28.1 J14.3 U8.7(DM3)
USB_HUB_DM4: D38.1 J38.3 U8.5(DM4)
USB_HUB_DP1: D25.1 J12.3(D+) U8.12(DP1)
USB_HUB_DP2: D27.1 J13.3(D+) U8.10(DP2)
USB_HUB_DP3: D29.1 J14.2 U8.8(DP3)
USB_HUB_DP4: D73.1 J38.2 U8.6(DP4)
WL_HOST_WAKE: J3.49
WL_REG_ON: J3.48
N16801073: J9.10(SH1) J9.11(SH2) L10.2
N16801211: C65.1 R56.2 U7.4(EN)
N16801228: R57.1 U7.3(ISET)
N16802593: D23.1 J11.1 R193.1
N16803235: R64.1 U8.15(DPU)
N16803237: R65.1 U8.14(DMU)
N16803510: C73.1 U8.3(XOUT) Y1.1
N16803514: C74.1 U8.4(XIN) Y1.3
N16803540: R66.1 U8.13(REXT)
N16803549: C72.1 R61.1 U8.17(VBUSM)
N16803553: R63.1 U8.16(XRSTJ)
N16803559: R62.1 U8.18(BUSJ)
N16804913: J12.5(SHELL_1) J12.6(SHELL_2) L11.2
N16810803: C77.1 R67.2 U9.4(EN)
N16810815: R68.1 U9.3(ISET)
N16816847: D33.1 J16.2 R72.1
N16816849: D32.1 J16.1 R71.1
N16825657: D53.1 J26.2 R139.1
N16825664: D52.1 J26.3 R140.1
N16825671: D51.1 J26.4 R141.1
N16825678: D50.1 J26.5 R142.1
N16825685: D49.1 J26.6 R143.1
N16825692: D48.1 J26.7 R144.1
N16827764: D59.1 J27.2 R145.1
N16827766: D58.1 J27.3 R146.1
N16827768: D57.1 J27.4 R147.1
N16827770: D56.1 J27.5 R148.1
N16827772: D55.1 J27.6 R149.1
N16869660: C151.1 U25.3(C1-)
N16869662: C151.2 U25.1(C1+)
N16869664: C152.1 U25.5(C2-)
N16869666: C152.2 U25.4(C2+)
N16869668: C155.1 U25.6(V-)
N16869670: C154.1 U25.2(V+)
N16869989: D66.1 R119.2
N16870097: D54.1 R109.2
N16870438: C148.1 U23.3(C1-)
N16870440: C148.2 U23.1(C1+)
N16870442: C149.1 U23.5(C2-)
N16870444: C149.2 U23.4(C2+)
N16870446: C147.1 U23.6(V-)
N16870448: C146.1 U23.2(V+)
N16948483: J13.5(SHELL_1) J13.6(SHELL_2) L12.2

Not connected (* = marked no-connect by the designer): J3 5* 85* 86*; U8 2(TESTJ)* 19(VDD5)* 21(DRV)* 22(LED1)* 23(LED2)* 24(PWRJ)*

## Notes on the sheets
sheet 1
- 200PIN 邮票孔
- GPIO4_B6
- VCC3V3_PMIC_RTC
- GPIO3_C6
- GPIO3_C1
- GPIO3_C5
- GPIO3_B6
- GPIO3_B4
- GPIO3_B5
- PWM12_M1
- GPIO3_B0
- GPIO3_A7
- SARADC0_IN4
- I2S2_MCLK_M0
- PCIE20_REFCLKP
- SARADC0_IN1
- PCIE20_REFCLKN
- SARADC0_IN0
- PCIE20_RXDP
- CAN1_RX_M1
- CAN1_TX_M1
- GPIO0_C0
- PCIE20_RXDN
- PCIE20_TXDP
- GPIO0_C3
- GPIO0_C1
- PCIE20_TXDN
- PWM0_M0
- GPIO0_C4
- CAN0_TX_M2
- GPIO0_C5
- GPIO0_C6
- CAN0_RX_M2
- GPIO0_C7
- GPIO0_B3
- GPIO0_B4
- GPIO0_A0
- GPIO0_B5
- GPIO0_A5
- GPIO0_B6
- GPIO0_B7
- GPIO0_A7
- GPIO0_A6
- BOARD ID: 0x0000, CH3: 电压0.3V, ADC值170
sheet 2
- RS232_1
- RS485-1
- GPIO3_B6
- 100R
- 100R
- 100R
- 100R
- 100R
- 100R
- RS232_2
- RS485-2
- GPIO3_C1
- 100R
- 100R
- 100R
- 100R
- 100R
- 100R
sheet 3
- TYPE-A USB3.0 OTG
- USB HUB1
- USB HUB2
- USB2.0 HUB PWR
- USB HUB3
- 排针
- GPIO0_C5
- 2A限流
- USB30_OTG0_ID低电平: Host模式
  USB30_OTG0_ID高电平: Device模式
- 默认为Device模式,设置为host模式需接上跳帽或者软件配置
- USB3.0 OTG PWR
- USB HUB4
- SARADC1
- GPIO0_C4
- 2A限流
- KLXES15AAA1*6
- USB2.0 HUB
- 按键接口
- SARADC0&1
- KLXES15AAA1*5
- Debug接口
- 18pF
- 18pF
- 兼容FE1.1s-BQFN24B
- 工业级：FE1.1s-BQFN24BT
